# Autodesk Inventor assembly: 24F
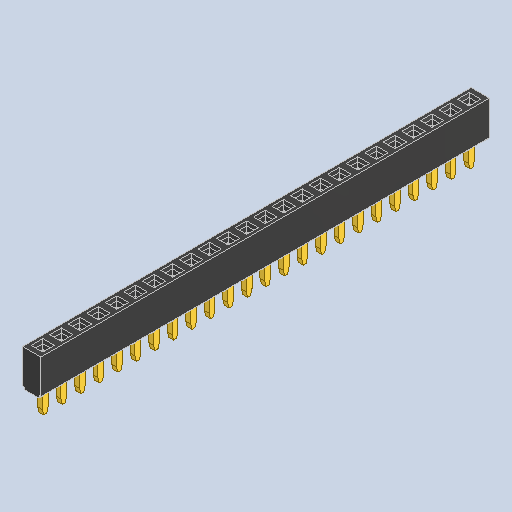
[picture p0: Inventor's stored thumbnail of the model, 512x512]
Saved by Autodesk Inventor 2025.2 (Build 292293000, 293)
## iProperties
Created: 2025-04
Part Number: 24F
Description: PART--DESC
Document SubType Name: Assembly
Designer: BennF
Author: BennF
Revision Number: NONE
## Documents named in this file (3)
- C:\Users\BennF\Nextcloud\Benutzer\CNC JarBeRi\existing parts\Electronics\RepRap A4988 Shied (USE WITHOUT ARDUINO)\reprap-a4988-1.snapshot.1\RepRap\RepRap\24F.iam
- C:\Users\BennF\Nextcloud\Benutzer\CNC JarBeRi\existing parts\Electronics\RepRap A4988 Shied (USE WITHOUT ARDUINO)\reprap-a4988-1.snapshot.1\RepRap\RepRap\24F Geometry.ipt
- C:\Users\BennF\Nextcloud\Benutzer\CNC JarBeRi\existing parts\Electronics\RepRap A4988 Shied (USE WITHOUT ARDUINO)\reprap-a4988-1.snapshot.1\RepRap\RepRap\Pin6.ipt
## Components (2 placed, 2 different names)
1. 24F Geometry
2. Pin6
